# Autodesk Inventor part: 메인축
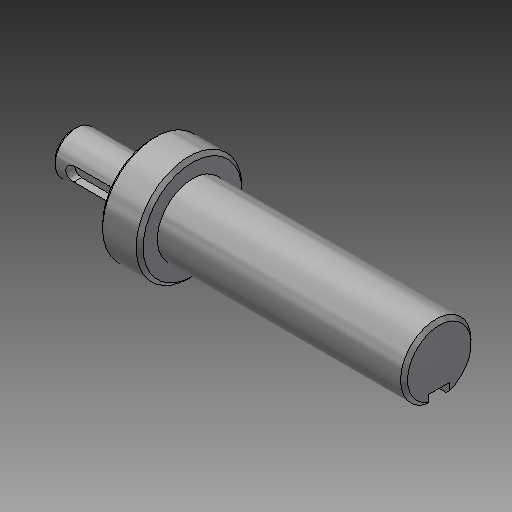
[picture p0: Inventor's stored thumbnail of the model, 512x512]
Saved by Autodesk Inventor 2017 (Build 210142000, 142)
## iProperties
Created: 2018-09
Part Number: 메인축
Document SubType Name: Modeling
Density: 7.86 g/cm^3
Material: 강철, 연강
Appearance: 강철
Mass: 251.949 g
Surface Area: 77.4412 cm^2
Volume: 32.0546 cm^3
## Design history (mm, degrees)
sketch "스케치1"
  geometry: L1 (34.997, -37.5)-(34.997, -77.5) reference; L2 (46.5, -38.401)-(46.5, -76.599) reference; L3 (12.497, -57.5)-(116.5, -57.5); L4 (12.497, -63.5)-(34.997, -63.5); L5 (34.997, -72.5)-(46.5, -72.5); L6 (46.5, -67.5)-(116.5, -67.5); L7 (116.5, -67.5)-(116.5, -57.5); L8 (12.497, -63.5)-(12.497, -57.5); 2 further points
  constraints: 12 end point, 5 point on line, 4 perpendicular, 1 midpoint, 1 parallel
  dimensions: "d0" = 20 diameter of L6 L3; "d1" = 30 diameter of L5 L3; "d2" = 22.5 distance of L4.start L4.end; "d3" = 70 distance of L6.start L6.end; "d5" = 12 diameter of L4 L3
revolve "회전1" sketch "스케치1" stored, may be unused: angle "d4" = 90 deg
chamfer "모따기1" distance "d6" = 1; stored, may be unused: second distance "d7" = 2, angle "d8" = 45 deg
node "작업 평면1"
sketch "스케치2"
  geometry: L1 (-11.25, -5)-(-11.25, 5) reference; L2 (-5.25, 2)-(4.75, 2); L3 (4.75, -2)-(-5.25, -2); A1 r 2 centre (4.75, 0) between (4.75, -2) and (4.75, 2); A2 r 2 centre (-5.25, 0) between (-5.25, 2) and (-5.25, -2); 2 further points
  constraints: 4 end point, 4 point on circle, 4 tangent, 2 centre point, 1 horizontal alignment, 1 midpoint, 1 parallel, 1 perpendicular
  dimensions: "d9" = 4 distance between parallel lines of L3 L2; "d10" = 14 dimension on A1 A2; "d11" = 4 distance edge to line of A2 L1
extrude "돌출1" cut sketch "스케치2" distance "d12" = 2.5; taper "d13" = 0 deg
node "작업 평면2"
sketch "스케치3"
  geometry: L1 (35, 9)-(35, -9) reference; L2 (35, 3)-(20, 3); L3 (20, -3)-(35, -3); A1 r 3 centre (20, 0) between (20, 3) and (20, -3); 2 further points
  constraints: 4 end point, 2 perpendicular, 2 point on circle, 2 point on line, 2 tangent, 1 centre point, 1 horizontal alignment, 1 midpoint
  dimensions: "d14" = 6 distance between parallel lines of L3 L2; "d15" = 18 dimension on A1 L1
extrude "돌출2" cut sketch "스케치3" distance "d16" = 3.5; taper "d17" = 0 deg
node "솔리드1"
node "참조1"
node "참조2"
